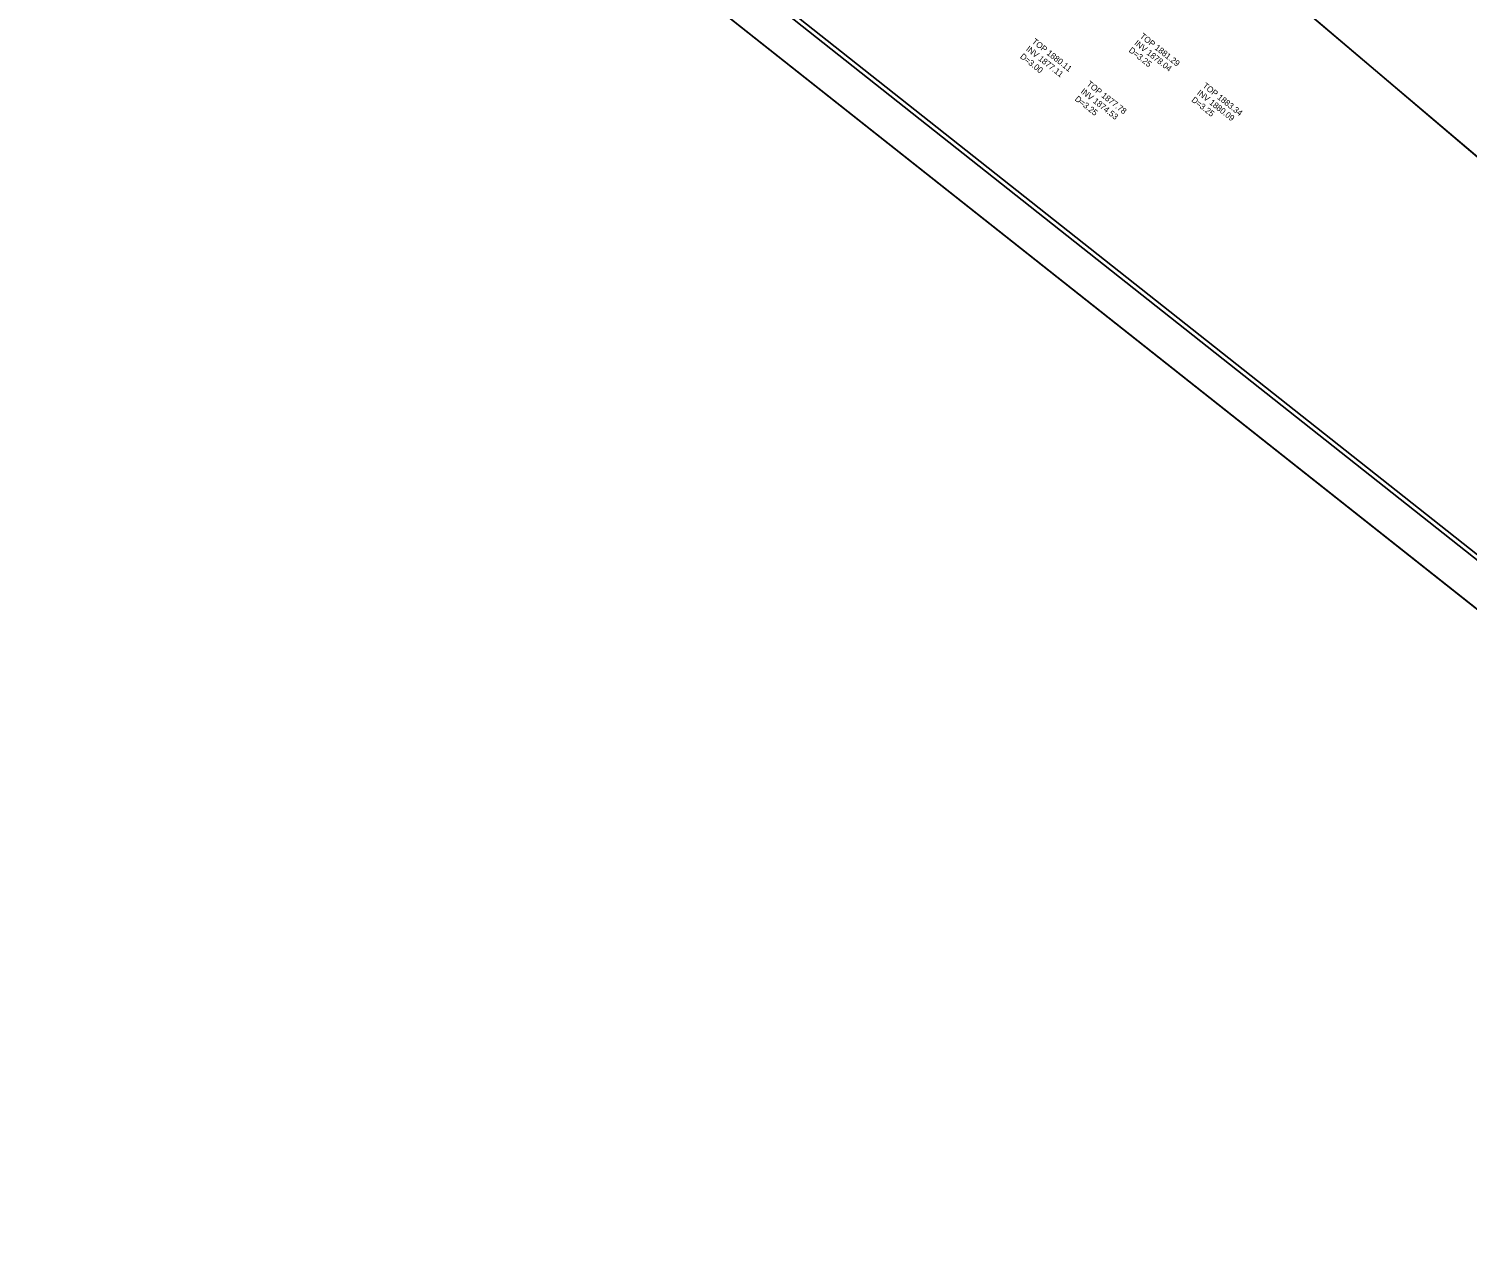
# Model space of a CAD drawing. Extents: x 557005 to 559009, y 505746 to 507841.
# Drawn here: x 557005 to 557843, y 505933 to 506649 of the extents above; entities that cross this region are included whole.
import ezdxf

# ---------------------------------------------------------------- set-up
doc = ezdxf.new("R2010")
doc.units = 0
for name, color, linetype in [('DTM Contours Minor Text', 7, 'Continuous'), ('Matchline', 7, 'Continuous'), ('Prop Horizontal Alignment Direction Label', 7, 'Continuous'), ('Prop SS Cut Line', 7, 'Continuous'), ('Prop SS Fill Line', 7, 'Continuous'), ('Scratch_Level_5', 7, 'Continuous'), ('Scratch_Level_9', 7, 'Continuous')]:
    doc.layers.add(name, color=color, linetype=linetype)

msp = doc.modelspace()

# ---------------------------------------------------------------- linework, layer by layer
at = {"layer": 'Matchline'}
msp.add_line((557889.73, 506539.36), (557425.46, 506933.59), dxfattribs=at)
at = {"layer": 'Prop Horizontal Alignment Direction Label'}
msp.add_lwpolyline([(559008.53, 506796.2), (557687.57, 507840.68), (557005.31, 506977.82), (558326.27, 505933.34)], close=True, dxfattribs=at)
at = {"layer": 'Prop SS Cut Line'}
msp.add_lwpolyline([(558979.69, 506787.13), (557803.06, 507717.49), (557151.81, 506893.85), (558328.44, 505963.5)], close=True, dxfattribs=at)
at = {"layer": 'Prop SS Fill Line'}
msp.add_lwpolyline([(558991.07, 506781.38), (557683.84, 507815), (557029.43, 506987.37), (558336.66, 505953.74)], close=True, dxfattribs=at)
at = {"layer": 'Scratch_Level_5'}
for points in [[(558502.21, 506199.86), (558069.07, 506542.35), (558000.13, 506451.2), (557930.66, 506511.32), (557889.73, 506539.36), (557425.46, 506933.59), (557395.12, 506959.79), (557368.13, 506966.2), (557439.22, 507142.63), (557392.13, 507195.25), (557803.85, 507716.87), (558807.23, 506891.56), (558715.12, 506775.08), (558872.03, 506651.01)], [(558502.21, 506199.86), (558069.07, 506542.35), (558000.13, 506451.2), (557930.66, 506511.32), (557889.73, 506539.36), (557425.46, 506933.59), (557395.12, 506959.79), (557474.03, 506970.73), (557439.22, 507142.63), (557392.13, 507195.25), (557803.85, 507716.87), (558807.23, 506891.56), (558715.12, 506775.08), (558872.03, 506651.01)]]:
    msp.add_lwpolyline(points, close=True, dxfattribs=at)
at = {"layer": 'Scratch_Level_9'}
msp.add_line((557005.31, 506977.82), (558326.27, 505933.34), dxfattribs=at)

# ---------------------------------------------------------------- texts
at = {"layer": 'DTM Contours Minor Text'}
for s, p in [('TOP 1881.29', (557651.92, 506643.92)), ('INV 1877.11', (557585.6, 506636.46)), ('TOP 1880.11', (557589.05, 506640.82)), ('D=3.25', (557645.41, 506635.69)), ('INV 1878.04', (557648.67, 506639.81)), ('D=3.00', (557582.15, 506632.1)), ('TOP 1877.78', (557620.92, 506616.12)), ('INV 1874.53', (557617.48, 506611.76)), ('INV 1880.09', (557685.17, 506610.94)), ('TOP 1883.34', (557688.43, 506615.06)), ('D=3.25', (557614.03, 506607.4)), ('D=3.25', (557681.91, 506606.82))]:
    msp.add_text(s, height=3.5, rotation=321.66667, dxfattribs=at).set_placement(p)

doc.saveas('drawing.dxf')
